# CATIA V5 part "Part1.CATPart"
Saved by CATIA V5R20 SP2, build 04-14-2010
Part number: Part1
Bounding box of the stored display mesh (mm): x -15 to 20, y -20.95 to 932.78, z -45.2 to 45.2
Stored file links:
  E:\CATIA\New folder\Part1.CATPart
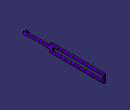
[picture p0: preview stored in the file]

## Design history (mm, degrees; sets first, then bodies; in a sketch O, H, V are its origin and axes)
Body1 (main body)
  Sketch1 on yz-plane, origin (0, 0, 0), H (0, 1, 0), V (0, 0, 1)
    construction line L1 (0, 0) -> (328.73, 0)
    line L2 (17.8051, 11.04) -> (281.82, 11.04)
    arc A1 centre (0, 0) radius 20.95 from (17.8051, -11.04) to (17.8051, 11.04) cw
    line L3 (295.86, 45.2) -> (932.78, 45.2)
    line L4 (932.78, 45.2) -> (932.78, -45.2)
    line L5 (932.78, -45.2) -> (295.86, -45.2)
    line L6 (295.86, -45.2) -> (295.86, -25.08)
    line L7 (326, 27.39) -> (919.1, 27.39)
    line L8 (919.1, 27.39) -> (919.1, -27.39)
    line L9 (919.1, -27.39) -> (326, -27.39)
    line L10 (326, -27.39) -> (326, -11.04)
    circle A2 centre (0, 0) radius 11.04
    line L11 (326, 0) -> (326, 27.39)
    line L12 (326, -11.04) -> (326, 0)
    line L13 (295.86, 25.08) -> (295.86, 45.2)
    line L14 (281.82, -11.04) -> (17.8051, -11.04)
    arc A3 centre (281.82, 25.08) radius 14.04 from (281.82, 11.04) to (295.86, 25.08) ccw
    arc A4 centre (281.82, -25.08) radius 14.04 from (281.82, -11.04) to (295.86, -25.08) cw
  MultiPad1: profile Sketch1, domains (length 0; length 20; length 20 / length 15)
